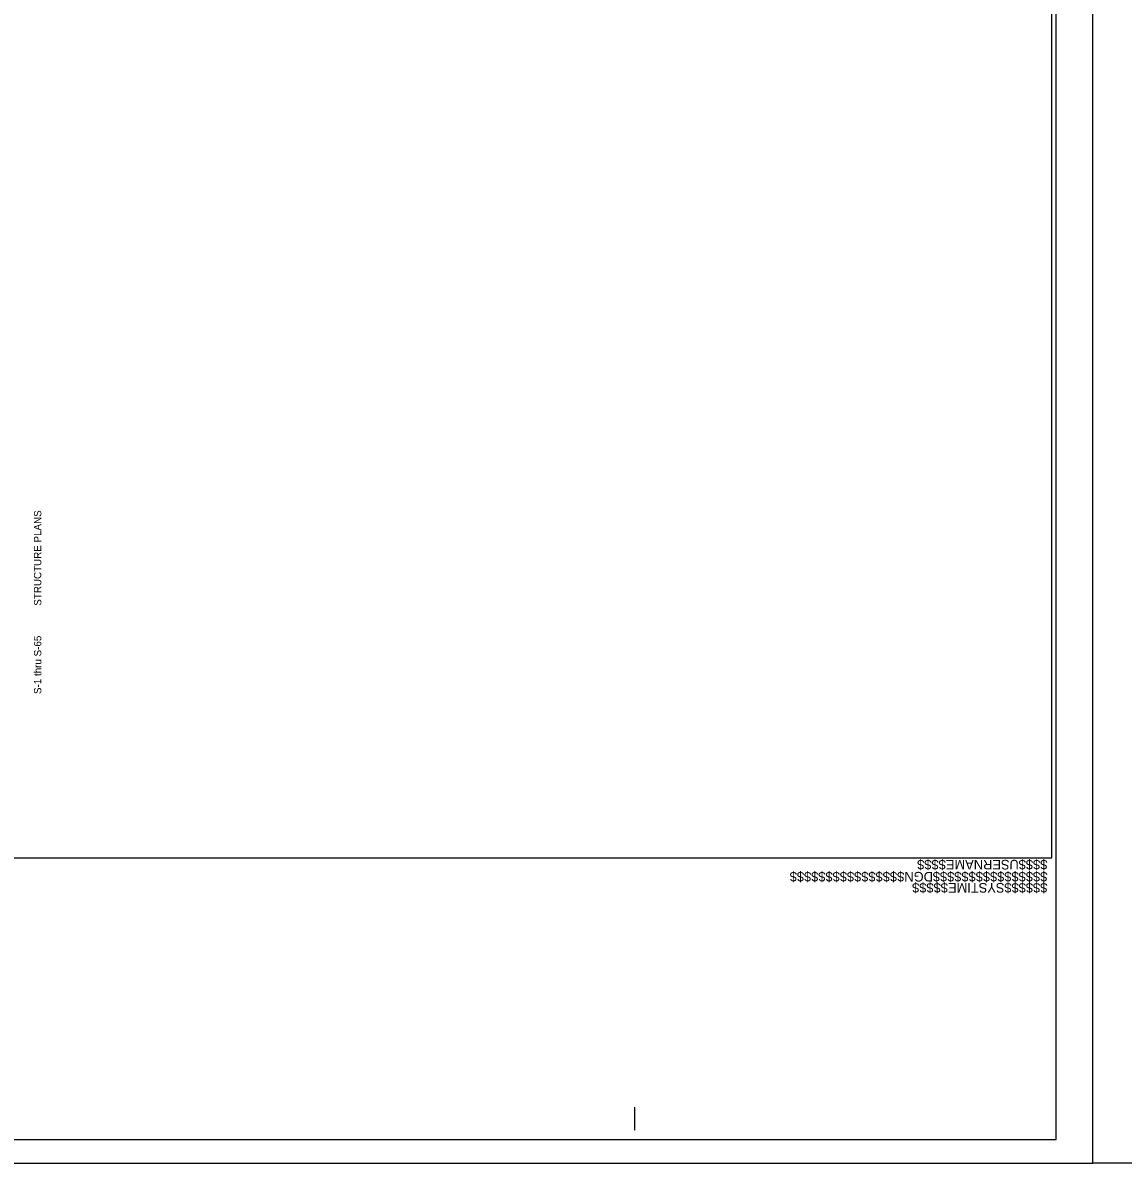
# Model space of a CAD drawing. Extents: x 2026893 to 2039781, y 729195 to 739590.
# Drawn here: x 2033032 to 2035133, y 733696 to 735872 of the extents above; entities that cross this region are included whole.
import ezdxf

# ---------------------------------------------------------------- set-up
doc = ezdxf.new("R2010")
doc.units = 0
for name, color, linetype in [('Old_Level_1', 7, 'Continuous'), ('Scratch_Level_3', 7, 'Continuous'), ('Sheet Cutting Line CELL', 7, 'Continuous'), ('Sheet Plan CELL', 7, 'Continuous'), ('Sheet Plot Border Inside CELL', 7, 'Continuous'), ('Sheet Plot Border Outside CELL', 7, 'Continuous')]:
    doc.layers.add(name, color=color, linetype=linetype)

msp = doc.modelspace()

# ---------------------------------------------------------------- linework, layer by layer
at = {"layer": 'Scratch_Level_3'}
msp.add_line((2035575.3, 733695.9), (2035075.3, 733695.9), dxfattribs=at)
at = {"layer": 'Sheet Cutting Line CELL'}
for p, q in [((2035075.3, 733695.9), (2035075.3, 739588.2)), ((2031242.8, 733695.9), (2035075.3, 733695.9))]:
    msp.add_line(p, q, dxfattribs=at)
at = {"layer": 'Sheet Plan CELL'}
for p, q in [((2034996.6, 734278.7), (2034996.6, 734278.7)), ((2034200.3, 733758.9), (2034200.3, 733802.7))]:
    msp.add_line(p, q, dxfattribs=at)
msp.add_lwpolyline([(2031321.6, 739528.7), (2031321.6, 734278.7), (2034996.6, 734278.7), (2034996.6, 739528.7)], close=True, dxfattribs=at)
at = {"layer": 'Sheet Plot Border Inside CELL'}
msp.add_lwpolyline([(2035005.3, 733741.4), (2035005.3, 739572.4), (2031312.8, 739572.4), (2031312.8, 733741.4)], close=True, dxfattribs=at)
at = {"layer": 'Sheet Plot Border Outside CELL'}
msp.add_lwpolyline([(2035075.3, 733695.9), (2035075.3, 739588.2), (2031242.8, 739588.2), (2031242.8, 733695.9)], close=True, dxfattribs=at)

# ---------------------------------------------------------------- texts
at = {"layer": 'Old_Level_1'}
msp.add_text('S-1 thru S-65           STRUCTURE PLANS', height=14, rotation=90, dxfattribs=at).set_placement((2033066.9, 734591.4))
at = {"layer": 'Sheet Plan CELL'}
for s, p in [('$$$$USERNAME$$$$', (2034988.3, 734274.9)), ('$$$$$$$$$$$$$$$$DGN$$$$$$$$$$$$$$$$', (2034988.3, 734251.9)), ('$$$$$$SYSTIME$$$$$', (2034988.3, 734230.7))]:
    msp.add_text(s, height=18.375, rotation=180, dxfattribs=at).set_placement(p)

doc.saveas('drawing.dxf')
